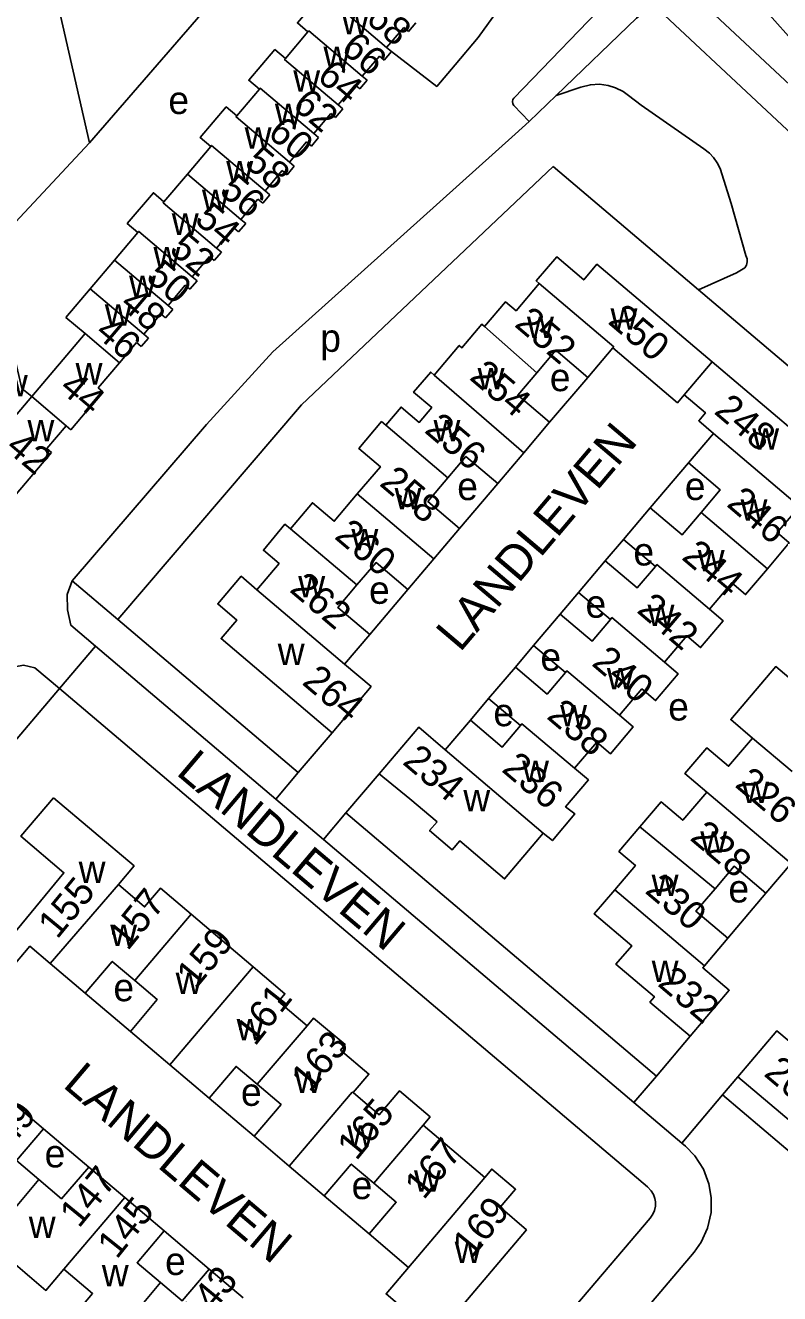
# Model space of a CAD drawing. Extents: x 155696 to 157795, y 382328 to 384028.
# Drawn here: x 156980.5 to 157088.9, y 382607.2 to 382789.6 of the extents above; entities that cross this region are included whole.
import ezdxf

# ---------------------------------------------------------------- set-up
doc = ezdxf.new("R2010")
doc.units = 0
for name, color, linetype in [('BLT_Basislijn', 7, 'Continuous'), ('BLT_Bebouwing', 7, 'Continuous'), ('BLT_Centroide', 7, 'Continuous'), ('BLT_Huisnummer', 7, 'Continuous'), ('BLT_Huisnummer_ tussenligend', 7, 'Continuous'), ('BLT_Onderverdeling_panden', 7, 'Continuous'), ('BLT_Straatnaam', 7, 'Continuous'), ('BLT_Vlakafsluiter', 7, 'Continuous')]:
    doc.layers.add(name, color=color, linetype=linetype)

msp = doc.modelspace()

# ---------------------------------------------------------------- linework, layer by layer
at = {"layer": 'BLT_Basislijn'}
for p, q in [((156989.72, 382772.65), (157013.94, 382800.66)), ((157069.01, 382778.09), (157067.22, 382779.49)), ((157078.05, 382771.82), (157069.01, 382778.09)), ((156989.72, 382772.65), (156975.39, 382757.33)), ((157020.2, 382735.01), (157056.36, 382769.27)), ((157061.35, 382738.95), (157055.86, 382732.49)), ((156993.81, 382704.12), (157020.2, 382735.01)), ((157070.34, 382720.18), (157075.82, 382726.65)), ((157048.41, 382723.7), (157042.93, 382717.23)), ((157063.87, 382712.55), (157066.49, 382715.65)), ((156993.81, 382704.12), (156987.23, 382709.69)), ((157035.48, 382708.44), (157030, 382701.97)), ((157057.4, 382704.92), (157060.03, 382708.02)), ((157019.74, 382682.14), (156993.81, 382704.12)), ((157050.94, 382697.3), (157053.56, 382700.39)), ((156938.34, 382638.74), (156985.4, 382694.2)), ((157044.47, 382689.67), (157047.1, 382692.77)), ((157024.59, 382687.86), (157019.74, 382682.14)), ((157019.74, 382682.14), (157016.5, 382678.32)), ((157031.37, 382681.96), (157026.59, 382676.33)), ((157026.59, 382676.33), (157023.36, 382672.51)), ((157071.23, 382638.49), (157026.59, 382676.33)), ((157086.96, 382664.79), (157081.48, 382658.32)), ((156995.59, 382644.91), (156989.08, 382650.43)), ((157076.07, 382644.21), (157071.23, 382638.49)), ((157071.23, 382638.49), (157067.99, 382634.67)), ((157082.94, 382638.39), (157080.73, 382635.78)), ((157013.38, 382629.83), (157006.9, 382635.32)), ((157080.73, 382635.78), (157074.86, 382628.86)), ((156983.12, 382630.92), (156989.63, 382625.41)), ((157029.93, 382615.79), (157023.46, 382621.28)), ((157000.44, 382616.22), (157006.94, 382610.75))]:
    msp.add_line(p, q, dxfattribs=at)
for points in [[(156978.64, 382830.73), (156976.68, 382829.71), (156989.72, 382772.65)], [(157053.84, 382820.07), (157054.45, 382819.24), (157055.88, 382816.34), (157057.06, 382812.77), (157057.11, 382807.89), (157056.9, 382806.75), (157056.1, 382804.15), (157054.16, 382800.54), (157051.31, 382795.79), (157045.61, 382787.83), (157042.27, 382783.89), (157039.64, 382780.77), (157033.12, 382785.78)], [(157181.21, 382688.84), (157179.43, 382690.1), (157176.42, 382697.44), (157171.41, 382704.63), (157166.61, 382709.99), (157160.01, 382715.97), (157130.85, 382743.22), (157078.2, 382792.43), (157081.81, 382796.54)], [(157100.35, 382776.62), (157085.5, 382793.3), (157081.81, 382796.54)], [(157050.74, 382778.02), (157050.56, 382778.29), (157050.51, 382778.59), (157050.57, 382778.88), (157050.74, 382779.11), (157065.41, 382794.36), (157068.11, 382796.29)], [(157156.59, 382712.32), (157127.44, 382739.57), (157071.65, 382791.71), (157070.72, 382791.71), (157069.85, 382791.52), (157069.01, 382791.13), (157068.33, 382790.61), (157056.81, 382779.46)], [(157067.22, 382779.49), (157066.42, 382780.04), (157065.34, 382780.59), (157064.26, 382780.92), (157063.03, 382781.08), (157061.73, 382781.02), (157060.35, 382780.68), (157056.81, 382779.46)], [(157052.94, 382775.74), (157056.81, 382779.46)], [(157052.94, 382775.74), (157050.74, 382778.02)], [(157050.9, 382773.9), (157052.94, 382775.74)], [(156987.23, 382709.69), (157006.52, 382732.17), (157016.07, 382742.63), (157050.9, 382773.9)], [(157080.37, 382768.97), (157079.95, 382769.78), (157079.41, 382770.55), (157078.83, 382771.18), (157078.05, 382771.82)], [(157077.26, 382751.55), (157056.36, 382769.27)], [(157084.09, 382756.48), (157081.96, 382763.94), (157080.37, 382768.97)], [(157083.95, 382754.71), (157084.17, 382755.1), (157084.28, 382755.57), (157084.26, 382756), (157084.09, 382756.48)], [(157077.26, 382751.55), (157082.74, 382753.97), (157083.95, 382754.71)], [(157080.73, 382635.78), (157106.14, 382614.24), (157161.8, 382679.9), (157077.26, 382751.55)], [(156990.56, 382700.32), (156987.04, 382703.3), (156986.57, 382705.52), (156986.52, 382707.71), (156987.23, 382709.69)], [(157016.5, 382678.32), (156990.56, 382700.32)], [(156975.91, 382696.33), (156977.76, 382697.07), (156980.24, 382697.56), (156981.87, 382697.2), (156985.4, 382694.2)], [(157048.94, 382592.94), (157070.3, 382618.06), (157070.69, 382618.62), (157070.95, 382619.18), (157071.09, 382619.81), (157071.1, 382620.41), (157071.01, 382620.88), (157070.79, 382621.48), (157070.44, 382622.01), (157069.92, 382622.56), (156985.4, 382694.2)], [(157067.99, 382634.67), (157023.36, 382672.51)], [(157077.97, 382625.1), (157076.75, 382627.01), (157075.39, 382628.41), (157074.86, 382628.86)], [(157028.66, 382556.57), (157076.63, 382613.16), (157077.66, 382614.62), (157078.57, 382616.63), (157079.07, 382618.87), (157079.11, 382621.03), (157078.77, 382623), (157077.97, 382625.1)]]:
    msp.add_lwpolyline(points, dxfattribs=at)
at = {"layer": 'BLT_Bebouwing'}
for p, q in [((157034.89, 382789.26), (157032.43, 382786.37)), ((157035.58, 382788.68), (157034.89, 382789.26)), ((157036.61, 382789.9), (157035.58, 382788.68)), ((157033.12, 382785.78), (157032.08, 382784.56)), ((157032.43, 382786.37), (157033.12, 382785.78)), ((157031.4, 382785.14), (157028.94, 382782.24)), ((157032.08, 382784.56), (157031.4, 382785.14)), ((157028.94, 382782.24), (157029.63, 382781.67)), ((157027.91, 382781.02), (157025.45, 382778.12)), ((157028.59, 382780.44), (157027.91, 382781.02)), ((157029.63, 382781.67), (157028.59, 382780.44)), ((157024.41, 382776.9), (157021.96, 382774.01)), ((157025.1, 382776.32), (157024.41, 382776.9)), ((157026.13, 382777.55), (157025.1, 382776.32)), ((157025.45, 382778.12), (157026.13, 382777.55)), ((157022.64, 382773.43), (157021.61, 382772.21)), ((157021.96, 382774.01), (157022.64, 382773.43)), ((157020.92, 382772.79), (157018.47, 382769.89)), ((157021.61, 382772.21), (157020.92, 382772.79)), ((157019.15, 382769.31), (157018.12, 382768.09)), ((157018.47, 382769.89), (157019.15, 382769.31)), ((157017.43, 382768.67), (157014.97, 382765.77)), ((157018.12, 382768.09), (157017.43, 382768.67)), ((157014.97, 382765.77), (157015.66, 382765.19)), ((157013.94, 382764.55), (157011.48, 382761.65)), ((157014.62, 382763.97), (157013.94, 382764.55)), ((157015.66, 382765.19), (157014.62, 382763.97)), ((157010.45, 382760.43), (157007.99, 382757.53)), ((157011.13, 382759.85), (157010.45, 382760.43)), ((157012.17, 382761.07), (157011.13, 382759.85)), ((157011.48, 382761.65), (157012.17, 382761.07)), ((157008.68, 382756.95), (157007.64, 382755.73)), ((157007.99, 382757.53), (157008.68, 382756.95)), ((157006.96, 382756.31), (157004.5, 382753.41)), ((157007.64, 382755.73), (157006.96, 382756.31)), ((157005.18, 382752.83), (157004.15, 382751.61)), ((157004.5, 382753.41), (157005.18, 382752.83)), ((157003.46, 382752.19), (157001.01, 382749.29)), ((157004.15, 382751.61), (157003.46, 382752.19)), ((157001.01, 382749.29), (157001.69, 382748.71)), ((156999.97, 382748.07), (156997.52, 382745.17)), ((157000.66, 382747.49), (156999.97, 382748.07)), ((157001.69, 382748.71), (157000.66, 382747.49)), ((156996.48, 382743.95), (156994.02, 382741.05)), ((156997.17, 382743.37), (156996.48, 382743.95)), ((156998.2, 382744.59), (156997.17, 382743.37)), ((156997.52, 382745.17), (156998.2, 382744.59)), ((156994.02, 382741.05), (156990.95, 382737.43)), ((156991.64, 382736.85), (156987.03, 382731.41)), ((156990.95, 382737.43), (156991.64, 382736.85)), ((156986.35, 382731.99), (156983.57, 382728.71)), ((156987.03, 382731.41), (156986.35, 382731.99)), ((156984.25, 382728.13), (156977.3, 382719.94)), ((156983.57, 382728.71), (156984.25, 382728.13)), ((157004.34, 382661.75), (157013.24, 382654.21)), ((156984.07, 382654.68), (156989.08, 382650.43)), ((156995.59, 382644.91), (157001.25, 382640.11)), ((157001.25, 382640.11), (157006.9, 382635.32)), ((156977.99, 382635.28), (156983.12, 382630.92)), ((157037.68, 382631.45), (157046.55, 382623.93)), ((157018.42, 382625.55), (157013.38, 382629.83)), ((156989.63, 382625.41), (156994.79, 382621.03)), ((157023.46, 382621.28), (157018.42, 382625.55)), ((156994.79, 382621.03), (157000.44, 382616.22)), ((157029.93, 382615.79), (157035.58, 382610.99)), ((157006.94, 382610.75), (157011.83, 382606.59))]:
    msp.add_line(p, q, dxfattribs=at)
for points in [[(157021.13, 382788.62), (157019.6, 382789.91), (157023.35, 382794.32), (157024.87, 382793.03)], [(157017.89, 382784.79), (157021.13, 382788.62)], [(157014.14, 382780.38), (157012.62, 382781.67), (157016.37, 382786.08), (157017.89, 382784.79)], [(157010.9, 382776.55), (157014.14, 382780.38)], [(157007.16, 382772.14), (157005.63, 382773.43), (157009.38, 382777.84), (157010.9, 382776.55)], [(157003.79, 382768.17), (157007.16, 382772.14)], [(157000.42, 382764.19), (157003.79, 382768.17)], [(156996.67, 382759.76), (156995.15, 382761.07), (156998.9, 382765.49), (157000.42, 382764.19)], [(156993.32, 382755.81), (156996.67, 382759.76)], [(156989.83, 382751.69), (156993.32, 382755.81)], [(157054.38, 382752.44), (157053.94, 382752.81), (157056.88, 382756.27), (157060.76, 382752.97), (157062.66, 382755.21), (157079.22, 382741.18)], [(156986.33, 382747.57), (156989.83, 382751.69)], [(157046.51, 382746.24), (157049.53, 382749.81), (157051.05, 382748.52), (157054.38, 382752.44)], [(156989.09, 382745.24), (156986.33, 382747.57)], [(157039.26, 382739.28), (157042.87, 382743.53), (157043.25, 382743.21), (157046.1, 382746.58), (157046.51, 382746.24)], [(156981.41, 382736.18), (156989.09, 382745.24)], [(156978.95, 382741.91), (156980, 382737.37), (156981.41, 382736.18), (156981.41, 382736.18)], [(157054.03, 382739.61), (157056.77, 382742.84), (157061.35, 382738.95)], [(157061.35, 382738.95), (157064.95, 382743.21)], [(157075.21, 382736.46), (157074.24, 382735.31), (157064.95, 382743.21)], [(157079.22, 382741.18), (157095.5, 382727.38), (157093.97, 382725.57), (157096.99, 382723.01), (157093.52, 382718.92), (157091.78, 382720.4)], [(157032.3, 382732.07), (157034.51, 382734.68), (157037.12, 382732.46), (157038.93, 382734.6), (157036.32, 382736.81), (157038.77, 382739.7), (157039.26, 382739.28)], [(157055.86, 382732.49), (157051.29, 382736.38), (157054.03, 382739.61)], [(157079.43, 382730.9), (157077.29, 382732.72), (157078.26, 382733.87), (157075.21, 382736.46)], [(157028.22, 382722.18), (157031.54, 382726.1), (157028.43, 382728.74), (157031.7, 382732.58), (157032.3, 382732.07)], [(157052.14, 382728.09), (157055.86, 382732.49)], [(157079.43, 382730.9), (157075.82, 382726.65)], [(157041.23, 382724.5), (157043.84, 382727.59), (157048.41, 382723.7)], [(157048.41, 382723.7), (157052.14, 382728.09)], [(157075.82, 382726.65), (157080.39, 382722.77), (157077.65, 382719.53)], [(157042.93, 382717.23), (157038.36, 382721.12), (157041.23, 382724.5)], [(157028.22, 382722.18), (157024.9, 382718.25), (157021.77, 382720.91), (157018.61, 382717.18)], [(157070.34, 382720.18), (157066.49, 382715.65)], [(157077.65, 382719.53), (157074.91, 382716.3), (157070.34, 382720.18)], [(157087.18, 382711.43), (157090.32, 382715.14), (157088.58, 382716.62), (157091.78, 382720.4)], [(157018.61, 382717.18), (157017.82, 382717.82), (157014.71, 382714.09), (157016.97, 382712.18), (157013.79, 382708.42)], [(157039.21, 382712.84), (157042.93, 382717.23)], [(157066.49, 382715.65), (157071.07, 382711.76)], [(157035.48, 382708.44), (157039.21, 382712.84)], [(157028.17, 382709.1), (157030.91, 382712.33), (157035.48, 382708.44)], [(157063.87, 382712.55), (157060.03, 382708.02)], [(157071.07, 382711.76), (157068.44, 382708.67), (157063.87, 382712.55)], [(157078.84, 382705.63), (157082.05, 382709.41), (157084.03, 382707.72), (157087.18, 382711.43)], [(157024.59, 382687.86), (157008.63, 382701.38), (157010.89, 382704.04), (157008.16, 382706.37), (157011.53, 382710.35), (157013.79, 382708.42)], [(157030, 382701.97), (157025.43, 382705.86), (157028.17, 382709.1)], [(157060.03, 382708.02), (157064.6, 382704.14)], [(157072.38, 382698), (157075.58, 382701.78), (157077.57, 382700.1), (157080.83, 382703.94), (157078.84, 382705.63)], [(157057.4, 382704.92), (157053.56, 382700.39)], [(157064.6, 382704.14), (157061.98, 382701.04), (157057.4, 382704.92)], [(157026.39, 382697.72), (157030, 382701.97)], [(157053.56, 382700.39), (157058.13, 382696.51)], [(157026.39, 382697.72), (157030.2, 382694.48), (157024.59, 382687.86)], [(157050.94, 382697.3), (157047.1, 382692.77)], [(157058.13, 382696.51), (157055.51, 382693.41), (157050.94, 382697.3)], [(157065.91, 382690.37), (157069.12, 382694.15), (157071.1, 382692.47), (157074.36, 382696.31), (157072.38, 382698)], [(157091.49, 382694.72), (157088.37, 382697.37), (157081.9, 382689.74), (157085.03, 382687.09)], [(157047.1, 382692.77), (157051.67, 382688.88)], [(157044.47, 382689.67), (157040.86, 382685.41)], [(157051.67, 382688.88), (157049.04, 382685.78), (157044.47, 382689.67)], [(157059.44, 382682.74), (157062.65, 382686.52), (157064.63, 382684.84), (157067.89, 382688.68), (157065.91, 382690.37)], [(157040.86, 382685.41), (157037.05, 382688.65), (157031.37, 382681.96)], [(157085.03, 382687.09), (157081.59, 382683.03), (157078.46, 382685.68), (157075.32, 382681.98), (157078.44, 382679.33)], [(157031.37, 382681.96), (157035.77, 382678.36), (157039.68, 382675.04)], [(157054.96, 382673.43), (157056.26, 382672.35), (157059.47, 382676.2), (157058.17, 382677.21), (157061.43, 382681.06), (157059.44, 382682.74)], [(156964.74, 382655.12), (156972.36, 382664.11), (156978.66, 382658.76), (156986.05, 382667.73), (156979.87, 382672.97), (156984.56, 382678.5)], [(156984.56, 382678.5), (156996.14, 382668.7), (156993.9, 382666.03)], [(157078.44, 382679.33), (157075, 382675.27), (157071.88, 382677.92), (157068.85, 382674.35)], [(157039.68, 382675.04), (157038.62, 382673.79), (157041.86, 382671.04), (157042.95, 382672.29), (157049.38, 382666.84), (157054.96, 382673.43)], [(157068.85, 382674.35), (157065.82, 382670.78), (157068.19, 382668.78), (157065.23, 382665.29)], [(157086.96, 382664.79), (157090.57, 382669.05)], [(157079.65, 382665.43), (157082.39, 382668.67), (157086.96, 382664.79)], [(156993.9, 382666.03), (156997.64, 382662.82), (156999.91, 382665.5), (157004.34, 382661.75)], [(157065.23, 382665.29), (157062.28, 382661.8), (157067.66, 382657.24), (157065.4, 382654.57), (157070.92, 382649.89), (157070.28, 382649.12), (157076.07, 382644.21)], [(157081.48, 382658.32), (157076.9, 382662.2), (157079.65, 382665.43)], [(157078.12, 382654.36), (157081.48, 382658.32)], [(156984.07, 382654.68), (156981.16, 382657.15), (156978.32, 382653.81), (156974.97, 382656.66), (156969.93, 382650.72)], [(156989.08, 382650.43), (156993, 382654.97), (156996.24, 382652.23)], [(157076.07, 382644.21), (157081.69, 382650.83), (157077.87, 382654.06), (157078.12, 382654.36)], [(157013.24, 382654.21), (157017.82, 382650.33), (157016.89, 382649.2), (157020.99, 382645.71)], [(156996.24, 382652.23), (156999.47, 382649.49), (156995.59, 382644.91)], [(157020.99, 382645.71), (157021.93, 382646.82), (157026.45, 382643.02), (157025.81, 382642.22), (157029.88, 382638.78), (157027.6, 382636.11)], [(157082.94, 382638.39), (157088.55, 382645.01), (157092.37, 382641.78)], [(157006.9, 382635.32), (157010.8, 382639.89), (157013.84, 382637.31)], [(157105.33, 382630.79), (157107.62, 382628.85), (157104.25, 382624.87), (157100.57, 382627.99), (157099.03, 382626.18), (157095.87, 382628.85), (157095.17, 382628.02), (157082.94, 382638.39)], [(157013.38, 382629.83), (157017.26, 382634.4), (157013.84, 382637.31)], [(157027.6, 382636.11), (157031.38, 382632.94), (157034.27, 382636.35), (157038.69, 382632.63), (157037.68, 382631.45)], [(156983.12, 382630.92), (156979.23, 382626.35), (156982.46, 382623.6)], [(156982.46, 382623.6), (156985.69, 382620.85), (156989.63, 382625.41)], [(157030.58, 382623.1), (157027.35, 382625.84), (157023.46, 382621.28)], [(157046.55, 382623.93), (157047.55, 382625.11), (157050.96, 382622.22), (157048.77, 382619.63), (157052.54, 382616.38), (157039.55, 382601.07)], [(157029.93, 382615.79), (157033.82, 382620.36), (157030.58, 382623.1)], [(157000.44, 382616.22), (156996.56, 382611.65), (156999.92, 382608.79)], [(156986.03, 382610.72), (156983.46, 382607.68), (156975, 382614.83)], [(156986.03, 382610.72), (156990.16, 382607.21), (156987.58, 382604.15), (156992.48, 382600), (156993.15, 382600.75)], [(156999.92, 382608.79), (157003.02, 382606.16), (157006.94, 382610.75)], [(157039.55, 382601.07), (157032.35, 382607.17), (157035.58, 382610.99)]]:
    msp.add_lwpolyline(points, dxfattribs=at)
at = {"layer": 'BLT_Onderverdeling_panden'}
for p, q in [((157003.79, 382768.17), (157011.48, 382761.65)), ((157001.01, 382749.29), (156993.32, 382755.81)), ((156997.52, 382745.17), (156989.83, 382751.69)), ((157046.51, 382746.24), (157054.03, 382739.61)), ((156989.09, 382745.24), (156994.02, 382741.05)), ((157079.22, 382741.18), (157075.21, 382736.46)), ((157052.14, 382728.09), (157039.26, 382739.28)), ((156981.41, 382736.18), (156975.96, 382729.75)), ((156986.35, 382731.99), (156981.41, 382736.18)), ((157032.3, 382732.07), (157041.23, 382724.5)), ((157091.78, 382720.4), (157079.43, 382730.9)), ((157028.22, 382722.18), (157039.21, 382712.84)), ((157028.17, 382709.1), (157018.61, 382717.18)), ((157013.79, 382708.42), (157026.39, 382697.72)), ((157054.96, 382673.43), (157040.86, 382685.41)), ((157090.72, 382682.27), (157085.03, 382687.09)), ((157078.44, 382679.33), (157090.57, 382669.05)), ((157079.65, 382665.43), (157068.85, 382674.35)), ((156993.9, 382666.03), (156984.07, 382654.68)), ((157065.23, 382665.29), (157078.12, 382654.36)), ((157004.34, 382661.75), (156996.24, 382652.23)), ((157013.24, 382654.21), (157001.25, 382640.11)), ((157020.99, 382645.71), (157013.84, 382637.31)), ((157037.68, 382631.45), (157030.58, 382623.1)), ((156975, 382614.83), (156982.46, 382623.6)), ((157046.55, 382623.93), (157035.58, 382610.99)), ((156986.03, 382610.72), (156994.79, 382621.03)), ((156993.15, 382600.75), (156999.92, 382608.79))]:
    msp.add_line(p, q, dxfattribs=at)
for points in [[(157032.43, 382786.37), (157024.74, 382792.88), (157024.87, 382793.03)], [(157021.13, 382788.62), (157021.25, 382788.76), (157028.94, 382782.24)], [(157025.45, 382778.12), (157017.76, 382784.64), (157017.89, 382784.79)], [(157021.96, 382774.01), (157014.27, 382780.52), (157014.14, 382780.38)], [(157010.9, 382776.55), (157010.78, 382776.4), (157018.47, 382769.89)], [(157014.97, 382765.77), (157007.28, 382772.29), (157007.16, 382772.14)], [(157007.99, 382757.53), (157000.3, 382764.05), (157000.42, 382764.19)], [(157004.5, 382753.41), (156996.81, 382759.93), (156996.67, 382759.76)], [(157064.95, 382743.21), (157065.08, 382743.36), (157054.38, 382752.44)], [(157077.65, 382719.53), (157087.18, 382711.43)], [(157078.84, 382705.63), (157071.29, 382712.03), (157071.07, 382711.76)], [(157072.38, 382698), (157064.82, 382704.4), (157064.6, 382704.14)], [(157065.91, 382690.37), (157058.36, 382696.77), (157058.13, 382696.51)], [(157059.44, 382682.74), (157051.89, 382689.14), (157051.67, 382688.88)], [(157027.6, 382636.11), (157027.49, 382636.2), (157018.42, 382625.55)]]:
    msp.add_lwpolyline(points, dxfattribs=at)
at = {"layer": 'BLT_Vlakafsluiter'}
for p, q in [((156985.4, 382694.2), (156990.56, 382700.32)), ((157016.5, 382678.32), (157023.36, 382672.51)), ((157067.99, 382634.67), (157074.86, 382628.86))]:
    msp.add_line(p, q, dxfattribs=at)

# ---------------------------------------------------------------- texts
at = {"layer": 'BLT_Centroide'}
for s, p in [('w', (157025.99, 382788.28)), ('w', (157023.35, 382783.44)), ('w', (157019.01, 382780.03)), ('e', (157001.06, 382776.81)), ('w', (157016.37, 382775.22)), ('w', (157012.03, 382771.81)), ('w', (157009.38, 382766.97)), ('w', (157005.89, 382762.84)), ('w', (157001.55, 382759.44)), ('w', (156998.91, 382754.62)), ('w', (156995.41, 382750.5)), ('w', (156991.92, 382746.38)), ('w', (157052.61, 382744.59)), ('w', (157064.62, 382745.79)), ('p', (157022.89, 382742.62)), ('w', (156987.72, 382737.92)), ('w', (157045.51, 382737.21)), ('e', (157055.89, 382736.96)), ('w', (156976.98, 382736.22)), ('w', (156980.8, 382729.75)), ('w', (157039.17, 382729.77)), ('w', (157084.99, 382728.57)), ('e', (157042.58, 382721.3)), ('e', (157075.3, 382721.31)), ('w', (157033.58, 382719.97)), ('w', (157083.31, 382718.33)), ('w', (157027.37, 382714.08)), ('e', (157067.91, 382711.9)), ('w', (157077.15, 382711.05)), ('w', (157019.73, 382707.3)), ('e', (157029.91, 382706.39)), ('e', (157061.02, 382704.39)), ('w', (157069.94, 382703.18)), ('w', (157016.78, 382697.57)), ('e', (157054.54, 382696.76)), ('w', (157064.09, 382694.1)), ('e', (157072.91, 382689.61)), ('e', (157047.78, 382688.79)), ('w', (157057.38, 382688.77)), ('w', (157051.91, 382680.79)), ('w', (157083.53, 382677.73)), ('w', (157043.46, 382676.56)), ('w', (157077.52, 382670.62)), ('w', (156988.16, 382666.25)), ('w', (157070.53, 382664.38)), ('e', (157081.57, 382663.45)), ('w', (156992.69, 382657.21)), ('w', (157070.53, 382652.03)), ('w', (157002.1, 382650.31)), ('e', (156993.16, 382649.25)), ('w', (157010.87, 382643.62)), ('w', (157019.23, 382636.08)), ('e', (157011.49, 382634.21)), ('w', (157026.76, 382628.34)), ('e', (156983.27, 382625.36)), ('e', (157027.4, 382620.8)), ('w', (157036.37, 382621.86)), ('w', (156980.99, 382615.22)), ('w', (157042.22, 382611.61)), ('e', (157000.59, 382609.89)), ('w', (156991.49, 382608.27))]:
    msp.add_text(s, height=4, dxfattribs=at).set_placement(p)
at = {"layer": 'BLT_Huisnummer'}
for s, rotation, p in [('66', 319.7112, (157025.68, 382785.92)), ('62', 319.7112, (157018.71, 382777.79)), ('58', 319.7112, (157011.8, 382769.5)), ('54', 319.7236, (157004.65, 382761.37)), ('50', 319.7236, (156997.65, 382753.1)), ('252', 319.7095, (157050.66, 382746.39)), ('46', 319.7148, (156990.35, 382745.09)), ('248', 319.7095, (157079.35, 382733.86)), ('256', 319.7095, (157037.71, 382731.15)), ('42', 319.7359, (156977.48, 382728.57)), ('260', 319.7095, (157024.78, 382715.89)), ('244', 319.7095, (157074.69, 382712.91)), ('240', 319.7095, (157061.76, 382697.65)), ('264', 319.7095, (157020.12, 382694.93)), ('234', 319.7095, (157034.57, 382683.47)), ('236', 319.7095, (157048.82, 382682.4)), ('228', 319.7095, (157075.88, 382672.56)), ('155', 50.5452, (156985.07, 382658.06)), ('159', 50.4075, (157004.96, 382650.85)), ('232', 319.7095, (157071.24, 382651.59)), ('163', 49.9715, (157021.41, 382635.99)), ('202', 319.7095, (157086.5, 382638.66)), ('167', 50.3555, (157037.76, 382620.58)), ('147', 50.7166, (156988.2, 382616.5)), ('169', 50.6324, (157044.66, 382612.13)), ('143', 50.5022, (157005.54, 382602.16))]:
    msp.add_text(s, height=4, rotation=rotation, dxfattribs=at).set_placement(p)
at = {"layer": 'BLT_Huisnummer_ tussenligend'}
for s, rotation, p in [('68', 319.7126, (157029.24, 382790.2)), ('64', 319.7112, (157022.24, 382781.89)), ('60', 319.7193, (157015.16, 382773.75)), ('56', 319.7076, (157008.21, 382765.49)), ('52', 319.7076, (157001.01, 382757.05)), ('48', 319.7119, (156993.91, 382749.18)), ('250', 319.7095, (157064.09, 382746.8)), ('254', 319.7095, (157044.18, 382738.77)), ('44', 319.7359, (156985.21, 382737.14)), ('258', 319.7095, (157031.25, 382723.52)), ('246', 319.7095, (157081.15, 382720.54)), ('262', 319.7095, (157018.33, 382708.25)), ('242', 319.7095, (157068.24, 382705.27)), ('238', 319.7095, (157055.29, 382690.02)), ('226', 319.7095, (157082.35, 382680.2)), ('230', 319.7095, (157069.42, 382664.94)), ('157', 50.9307, (156995.21, 382656.39)), ('161', 51.6551, (157013.51, 382642.67)), ('149', 50.1819, (156976.56, 382625.93)), ('165', 50.6477, (157028.08, 382626.21)), ('145', 51.3269, (156993.64, 382612.04))]:
    msp.add_text(s, height=4, rotation=rotation, dxfattribs=at).set_placement(p)
at = {"layer": 'BLT_Straatnaam'}
for rotation, p in [(49.7122, (157042.99, 382699.31)), (319.7122, (157002.02, 382681.95)), (319.7122, (156985.73, 382637.02))]:
    msp.add_text('LANDLEVEN', height=5, rotation=rotation, dxfattribs=at).set_placement(p)

doc.saveas('drawing.dxf')
